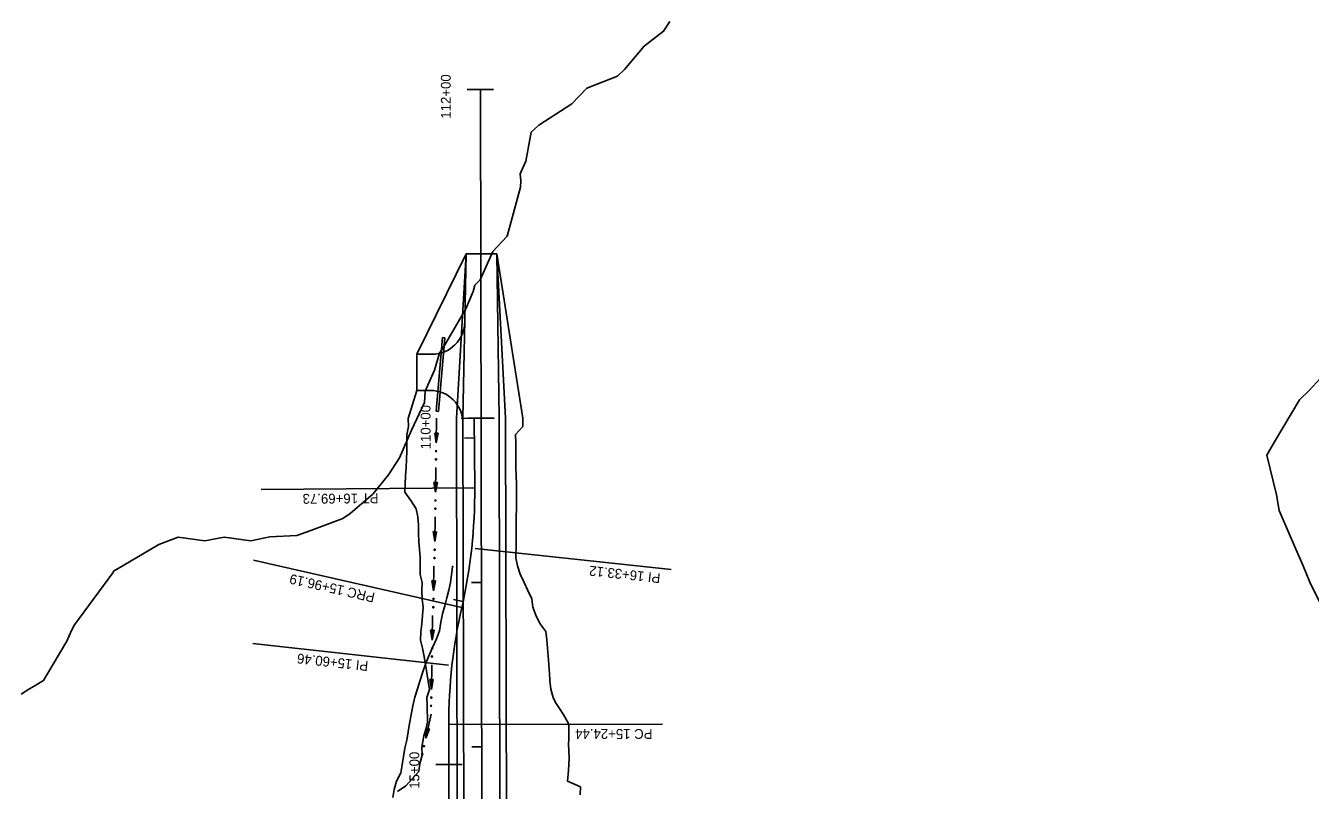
# Model space of a CAD drawing. Extents: x 1395202 to 1465904, y 1787951 to 1846942.
# Drawn here: x 1405502 to 1406284, y 1842571 to 1843037 of the extents above; entities that cross this region are included whole.
import ezdxf

# ---------------------------------------------------------------- set-up
doc = ezdxf.new("R2010")
doc.units = 0
for name, color, linetype in [('R_Drainage', 7, 'Continuous'), ('R_Horz Alg', 7, 'Continuous'), ('R_Horz Alg Stationing', 7, 'Continuous'), ('R_Perimeter', 7, 'Continuous'), ('R_Proposed Lane', 7, 'Continuous'), ('R_Proposed Shoulder', 7, 'Continuous'), ('R_SFHA', 7, 'Continuous'), ('R_Special Ditch', 7, 'Continuous'), ('R_Temp Perimeter', 7, 'Continuous'), ('R_Temp_Horz Alg', 7, 'Continuous'), ('R_Temp_Horz Alg Annot', 7, 'Continuous'), ('R_Temp_Horz Alg Stationing', 7, 'Continuous')]:
    doc.layers.add(name, color=color, linetype=linetype)

msp = doc.modelspace()

# ---------------------------------------------------------------- linework, layer by layer
at = {"layer": 'R_Drainage'}
for p, q in [((1405752.19, 1842802), (1405756.09, 1842846.83)), ((1405757.59, 1842846.7), (1405753.68, 1842801.87)), ((1405757.59, 1842846.7), (1405756.09, 1842846.83)), ((1405753.68, 1842801.87), (1405752.19, 1842802))]:
    msp.add_line(p, q, dxfattribs=at)
at = {"layer": 'R_Horz Alg'}
msp.add_line((1405780.08, 1842528.16), (1405779.12, 1842997.71), dxfattribs=at)
msp.add_line((1405780.08, 1842528.16), (1405779.12, 1842997.71), dxfattribs=at)
at = {"layer": 'R_Horz Alg Stationing'}
for points in [[(1405771.12, 1842997.69), (1405787.12, 1842997.73)], [(1405771.12, 1842997.69), (1405787.12, 1842997.73)], [(1405773.32, 1842897.7), (1405779.32, 1842897.71)], [(1405771.53, 1842797.69), (1405787.53, 1842797.73)], [(1405773.73, 1842697.7), (1405779.73, 1842697.71)], [(1405773.93, 1842597.7), (1405779.93, 1842597.71)]]:
    msp.add_lwpolyline(points, dxfattribs=at)
at = {"layer": 'R_Perimeter'}
msp.add_lwpolyline([(1405728.74, 1842570.53), (1405733.71, 1842573.99), (1405741.59, 1842582.63), (1405742.3, 1842587.63), (1405743.73, 1842592.64), (1405743.54, 1842597.47), (1405744.63, 1842604.36), (1405746.14, 1842609.09), (1405747.01, 1842612.64), (1405746.77, 1842622.64), (1405746.65, 1842627.64), (1405748.18, 1842632.65), (1405747.38, 1842637.64), (1405746.58, 1842642.64), (1405746.34, 1842644.16), (1405745.77, 1842647.64), (1405744.88, 1842652.64), (1405743.84, 1842657.64), (1405742.78, 1842662.64), (1405742.8, 1842667.64), (1405743.49, 1842672.64), (1405743.89, 1842677.64), (1405744.28, 1842682.64), (1405743.78, 1842687.64), (1405743.58, 1842692.64), (1405743.61, 1842697.64), (1405742.56, 1842702.63), (1405742.49, 1842707.63), (1405742.39, 1842712.63), (1405742.24, 1842715.58), (1405742.1, 1842717.63), (1405741.77, 1842722.63), (1405741.52, 1842727.63), (1405741.45, 1842732.63), (1405741.15, 1842737.63), (1405740.15, 1842742.63), (1405736.73, 1842747.62), (1405733.09, 1842752.62), (1405733.33, 1842757.62), (1405733.63, 1842762.62), (1405733.92, 1842767.62), (1405734.21, 1842772.62), (1405734.31, 1842777.62), (1405734.31, 1842782.62), (1405734.46, 1842787.62), (1405735.46, 1842792.62), (1405735.09, 1842797.62), (1405740.49, 1842814.63), (1405740.45, 1842836.63), (1405770.46, 1842897.69), (1405789.1, 1842897.73), (1405805.05, 1842797.76), (1405805.03, 1842792.76), (1405800.55, 1842787.75), (1405800.65, 1842782.75), (1405800.75, 1842772.75), (1405800.81, 1842767.75), (1405800.91, 1842762.75), (1405801.07, 1842757.75), (1405801.06, 1842752.75), (1405801.05, 1842747.75), (1405801.04, 1842742.75), (1405801.02, 1842737.75), (1405801, 1842732.75), (1405800.98, 1842727.75), (1405800.96, 1842722.75), (1405800.83, 1842717.75), (1405800.8, 1842715.7), (1405800.74, 1842712.75), (1405801.68, 1842707.76), (1405803.39, 1842702.76), (1405805.72, 1842697.76), (1405808.1, 1842692.77), (1405810.42, 1842687.77), (1405811.16, 1842682.77), (1405812.89, 1842677.78), (1405815.37, 1842672.78), (1405819.05, 1842667.79), (1405819.69, 1842662.79), (1405820.07, 1842657.79), (1405820.45, 1842652.79), (1405820.83, 1842647.79), (1405821.08, 1842644.31), (1405821.16, 1842642.79), (1405821.43, 1842637.8), (1405822.01, 1842632.8), (1405823.51, 1842627.8), (1405824.89, 1842624.7), (1405826.9, 1842621.61), (1405830.02, 1842617.03), (1405830.02, 1842617.03), (1405830.02, 1842617.03), (1405832.91, 1842611.45), (1405832.91, 1842608.45), (1405832.92, 1842602.45), (1405832.86, 1842599.6), (1405833.14, 1842590.77), (1405832.76, 1842583.19), (1405832.18, 1842576.87), (1405832.18, 1842576.78), (1405840.05, 1842573.34), (1405839.93, 1842568.52)], dxfattribs=at)
at = {"layer": 'R_Proposed Lane'}
for p, q in [((1405768.53, 1842797.69), (1405770.46, 1842897.69)), ((1405790.53, 1842797.73), (1405789.1, 1842897.73)), ((1405740.45, 1842836.63), (1405749.71, 1842836.65)), ((1405740.45, 1842836.63), (1405740.49, 1842814.63)), ((1405740.49, 1842814.63), (1405748.49, 1842814.65)), ((1405769.08, 1842528.24), (1405768.53, 1842797.69)), ((1405791.07, 1842528.28), (1405790.53, 1842797.73))]:
    msp.add_line(p, q, dxfattribs=at)
for centre, start, end in [((1405749.66, 1842856.65), 270.11667, 358.89054), ((1405748.53, 1842794.65), 0.11667, 90.11667)]:
    msp.add_arc(centre, 20, start, end, dxfattribs=at)
at = {"layer": 'R_Proposed Shoulder'}
for p, q in [((1405764.53, 1842797.68), (1405770.46, 1842897.69)), ((1405794.53, 1842797.74), (1405789.1, 1842897.73)), ((1405765.08, 1842528.23), (1405764.53, 1842797.68)), ((1405795.07, 1842528.29), (1405794.53, 1842797.74))]:
    msp.add_line(p, q, dxfattribs=at)
at = {"layer": 'R_SFHA'}
for points in [[(1405499.52, 1842629.84), (1405504.33, 1842632.77), (1405507.5, 1842634.7), (1405513.12, 1842638.13), (1405514.6, 1842640.59), (1405527.44, 1842661.98), (1405530.28, 1842668.44), (1405532.01, 1842671.88), (1405555.34, 1842703.66), (1405556.11, 1842704.73), (1405557.66, 1842705.66), (1405583.32, 1842720.74), (1405595.17, 1842725.2), (1405611.33, 1842723.07), (1405623.2, 1842725.27), (1405639.36, 1842723.03), (1405651.04, 1842725.58), (1405667.37, 1842726.28), (1405675.99, 1842729.34), (1405695.37, 1842736.58), (1405699.84, 1842739.78), (1405713.63, 1842751.5), (1405723.31, 1842763.25), (1405729.82, 1842773.57), (1405737.17, 1842790.52), (1405745.13, 1842807.31), (1405745.48, 1842814.16), (1405751.14, 1842826.91), (1405754.29, 1842837.22), (1405756.79, 1842841.04), (1405770.27, 1842864.22), (1405774.81, 1842874.79), (1405775.74, 1842878.73), (1405779, 1842882), (1405786.79, 1842899.1), (1405795.47, 1842908.55), (1405803.66, 1842938.43), (1405803.77, 1842942.28), (1405803.32, 1842946.49), (1405806.81, 1842954.22), (1405810.16, 1842971.9), (1405814.77, 1842976.01), (1405834.73, 1842989.01), (1405843.99, 1842998.61), (1405862.7, 1843005.96), (1405866.82, 1843009.86), (1405878.83, 1843024.13), (1405890.64, 1843033.2), (1405894.39, 1843039.11)], [(1406290.43, 1842821.88), (1406283.64, 1842814.53), (1406277.66, 1842808.92), (1406262.53, 1842783.37), (1406257.8, 1842775.16), (1406263.75, 1842751.03), (1406265.46, 1842741.49), (1406275.46, 1842718.01), (1406279.96, 1842707.84), (1406283.99, 1842698.01), (1406291.43, 1842683.06)]]:
    msp.add_lwpolyline(points, dxfattribs=at)
at = {"layer": 'R_Special Ditch'}
for p, q in [((1405752.29, 1842782.66), (1405752.51, 1842797.66)), ((1405753.44, 1842788.64), (1405751.32, 1842788.67)), ((1405751.32, 1842788.67), (1405752.29, 1842782.66)), ((1405752.29, 1842782.66), (1405753.44, 1842788.64)), ((1405751.86, 1842752.66), (1405752.08, 1842767.65)), ((1405752.07, 1842767.66), (1405752.07, 1842767.62)), ((1405753, 1842758.64), (1405750.89, 1842758.67)), ((1405750.89, 1842758.67), (1405751.86, 1842752.66)), ((1405751.86, 1842752.66), (1405753, 1842758.64)), ((1405751.34, 1842722.65), (1405751.56, 1842737.65)), ((1405751.64, 1842737.66), (1405751.64, 1842737.62)), ((1405752.48, 1842728.64), (1405750.37, 1842728.67)), ((1405750.37, 1842728.67), (1405751.34, 1842722.65)), ((1405751.34, 1842722.65), (1405752.48, 1842728.64)), ((1405750.62, 1842692.67), (1405750.84, 1842707.67)), ((1405751.12, 1842707.66), (1405751.12, 1842707.62)), ((1405751.76, 1842698.65), (1405749.65, 1842698.68)), ((1405749.65, 1842698.68), (1405750.62, 1842692.67)), ((1405750.62, 1842692.67), (1405751.76, 1842698.65)), ((1405749.85, 1842662.67), (1405750.07, 1842677.66)), ((1405750.4, 1842677.67), (1405750.4, 1842677.63)), ((1405750.99, 1842668.65), (1405748.88, 1842668.68)), ((1405748.88, 1842668.68), (1405749.85, 1842662.67)), ((1405749.85, 1842662.67), (1405750.99, 1842668.65)), ((1405749.33, 1842632.67), (1405749.55, 1842647.66)), ((1405749.63, 1842647.67), (1405749.63, 1842647.63)), ((1405750.47, 1842638.65), (1405748.36, 1842638.68)), ((1405748.36, 1842638.68), (1405749.33, 1842632.67)), ((1405749.33, 1842632.67), (1405750.47, 1842638.65)), ((1405745.88, 1842603), (1405749.11, 1842617.65)), ((1405749.11, 1842617.67), (1405749.11, 1842617.63)), ((1405746.14, 1842609.09), (1405745.88, 1842603)), ((1405745.88, 1842603), (1405748.2, 1842608.63)), ((1405748.2, 1842608.63), (1405746.14, 1842609.09)), ((1405742.65, 1842588.35), (1405742.64, 1842588.31))]:
    msp.add_line(p, q, dxfattribs=at)
for centre in [(1405752.18, 1842772.64), (1405752.25, 1842777.65), (1405751.82, 1842747.65), (1405751.75, 1842742.64), (1405751.3, 1842717.65), (1405751.23, 1842712.64), (1405750.58, 1842687.66), (1405750.51, 1842682.65), (1405749.81, 1842657.66), (1405749.74, 1842652.65), (1405749.22, 1842622.65), (1405749.29, 1842627.66), (1405743.76, 1842593.21), (1405744.84, 1842598.1)]:
    msp.add_circle(centre, 0.375, dxfattribs=at)
at = {"layer": 'R_Temp Perimeter'}
msp.add_lwpolyline([(1405725.8, 1842566.79), (1405726.66, 1842571.79), (1405728.02, 1842576.79), (1405730.7, 1842581.8), (1405731.55, 1842586.8), (1405732.38, 1842591.8), (1405733.17, 1842596.8), (1405734.32, 1842601.81), (1405735.11, 1842606.81), (1405735.92, 1842611.85), (1405736.98, 1842617.21), (1405738.1, 1842622.54), (1405739.26, 1842627.84), (1405740.79, 1842633.08), (1405742.53, 1842638.27), (1405744.17, 1842643.43), (1405745.91, 1842648.54), (1405748, 1842653.57), (1405750.16, 1842658.54), (1405752.49, 1842663.44), (1405754.36, 1842668.38), (1405755.03, 1842673.5), (1405756, 1842678.58), (1405757.44, 1842683.56), (1405758.81, 1842688.29), (1405759.96, 1842692.99), (1405760.93, 1842697.74), (1405761.64, 1842702.54), (1405762.27, 1842707.34), (1405762.33, 1842707.84)], dxfattribs=at)
at = {"layer": 'R_Temp_Horz Alg'}
for p, q in [((1405775.71, 1842755.4), (1405775.39, 1842797.67)), ((1405760.1, 1842515.27), (1405759.91, 1842611.3))]:
    msp.add_line(p, q, dxfattribs=at)
for centre, start, end in [((1405457.41, 1842752.96), 347.20209, 0.43917), ((1406078.22, 1842611.94), 167.20209, 180.11667)]:
    msp.add_arc(centre, 318.31, start, end, dxfattribs=at)
at = {"layer": 'R_Temp_Horz Alg Annot'}
for points in [[(1405775.71, 1842755.4), (1405645.71, 1842754.41)], [(1405775.99, 1842718.47), (1405895.3, 1842705.55)], [(1405767.81, 1842682.45), (1405641.04, 1842711.25)], [(1405759.83, 1842647.32), (1405640.57, 1842660.58)], [(1405759.91, 1842611.3), (1405889.91, 1842611.56)]]:
    msp.add_lwpolyline(points, dxfattribs=at)
at = {"layer": 'R_Temp_Horz Alg Stationing'}
for points in [[(1405767.39, 1842797.61), (1405783.39, 1842797.73)], [(1405767.39, 1842797.61), (1405783.39, 1842797.73)], [(1405769.48, 1842785.63), (1405775.48, 1842785.68)], [(1405762.77, 1842687.44), (1405768.64, 1842686.18)], [(1405751.96, 1842586.84), (1405767.96, 1842586.87)]]:
    msp.add_lwpolyline(points, dxfattribs=at)

# ---------------------------------------------------------------- texts
at = {"layer": 'R_Horz Alg Stationing'}
for s, p in [('112+00', (1405761.16, 1842980.03)), ('112+00', (1405761.16, 1842980.03)), ('110+00', (1405748.84, 1842778.75))]:
    msp.add_text(s, height=6, rotation=90.11667, dxfattribs=at).set_placement(p)
at = {"layer": 'R_Temp_Horz Alg Annot'}
for s, rotation, p in [('PT 16+69.73', 180.43917, (1405717.11, 1842751.96)), ('PRC 15+96.19', 167.20209, (1405715.36, 1842691.29)), ('PI 16+33.12', 173.82063, (1405889.01, 1842703.22)), ('PI 15+60.46', 173.65938, (1405711.17, 1842649.71)), ('PC 15+24.44', 180.11667, (1405883.91, 1842608.55))]:
    msp.add_text(s, height=6, rotation=rotation, dxfattribs=at).set_placement(p)
at = {"layer": 'R_Temp_Horz Alg Stationing'}
msp.add_text('15+00', height=6, rotation=90.11667, dxfattribs=at).set_placement((1405741.99, 1842572.18))

doc.saveas('drawing.dxf')
